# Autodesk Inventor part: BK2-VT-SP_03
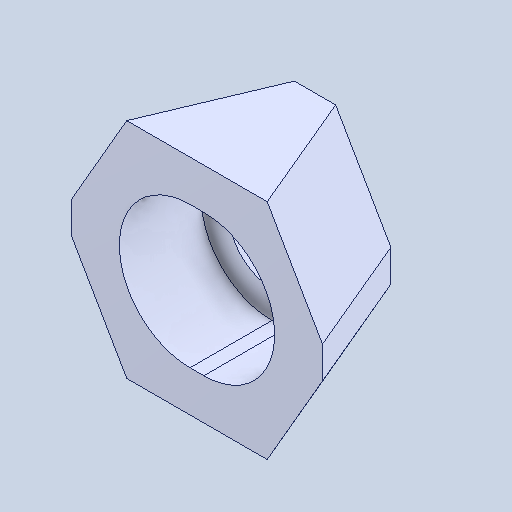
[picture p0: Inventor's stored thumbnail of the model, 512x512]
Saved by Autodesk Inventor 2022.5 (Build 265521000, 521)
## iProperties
Created: 2024-08
Part Number: BK2-VT-SP_03
Material: 一般
Document SubType Name: Modeling
Designer: ImaoCorp
Density: 1 g/cm^3
Appearance: 既定
Author: ImaoCorp
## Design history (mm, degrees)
feature "BK2-VT-SP_03"
node "ソリッド1"
